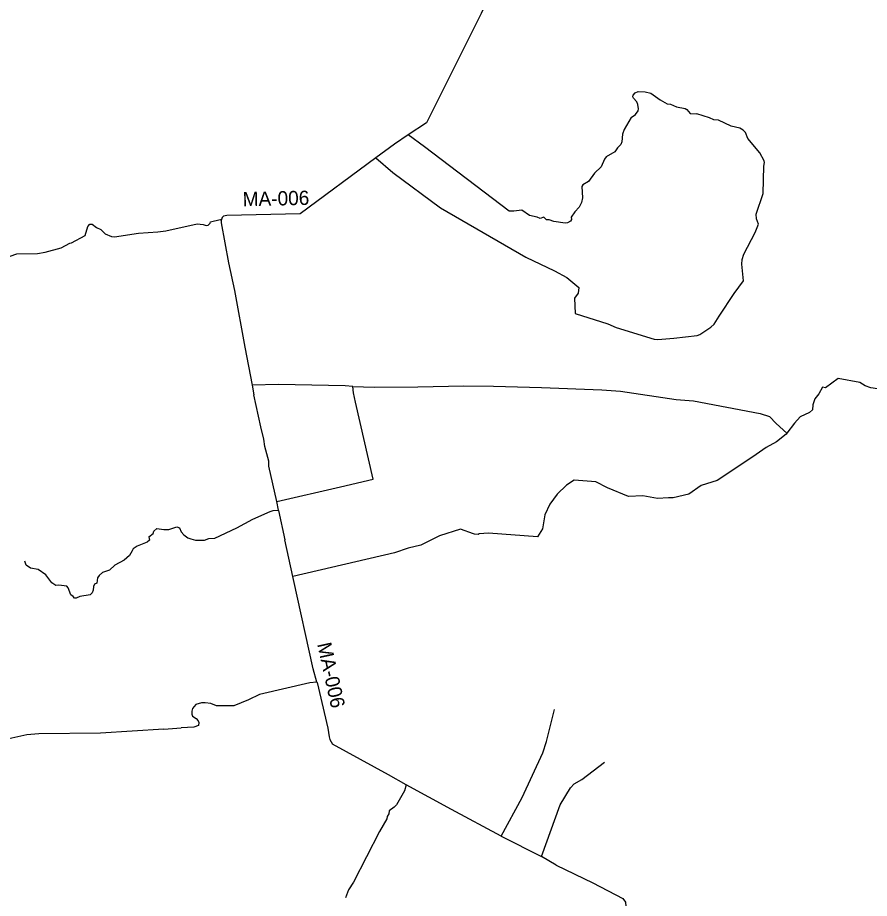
# Model space of a CAD drawing. Extents: x 332 to 501, y 9447 to 9559.
# Drawn here: x 358.33 to 381.07, y 9470.52 to 9494.03 of the extents above; entities that cross this region are included whole.
import ezdxf

# ---------------------------------------------------------------- set-up
doc = ezdxf.new("R2010")
doc.units = 0
for name, color, linetype in [('Level 2', 7, 'Continuous'), ('Level 31', 7, 'Continuous'), ('Level 5', 7, 'Continuous')]:
    doc.layers.add(name, color=color, linetype=linetype)

msp = doc.modelspace()

# ---------------------------------------------------------------- linework, layer by layer
at = {"layer": 'Level 2'}
for points in [[(370.6661, 9496.9394), (371.4317, 9495.8895), (371.441, 9495.7173), (370.7059, 9494.1339), (369.2463, 9491.221), (368.7582, 9490.8961)], [(368.7582, 9490.8961), (368.393, 9490.6531), (367.8945, 9490.2849)], [(367.8945, 9490.2849), (365.8781, 9488.7948), (363.9176, 9488.7487), (363.8245, 9488.7254), (363.7966, 9488.6928), (363.7677, 9488.6105)], [(363.7677, 9488.6105), (363.764, 9488.5484), (363.9584, 9487.4823), (364.1226, 9486.7456)], [(364.1226, 9486.7456), (364.401, 9485.2331)], [(364.401, 9485.2331), (364.5932, 9484.2177)], [(364.5932, 9484.2177), (364.6419, 9483.9606)], [(365.2484, 9481.1136), (365.0374, 9482.053), (365.0374, 9482.1898), (364.9338, 9482.5836), (364.9096, 9482.7777), (364.8214, 9483.1053), (364.6419, 9483.9606)], [(365.2987, 9480.8784), (365.2484, 9481.1136)], [(365.2998, 9480.873), (365.2987, 9480.8784)], [(365.2998, 9480.873), (365.469, 9480.085)], [(365.6771, 9479.1125), (365.469, 9480.085)], [(365.6964, 9479.0285), (365.6771, 9479.1125)], [(366.324, 9476.2857), (366.224, 9476.649), (365.6964, 9479.0285)], [(366.3253, 9476.2811), (366.324, 9476.2857)], [(366.3253, 9476.2811), (366.6141, 9475.064), (366.6494, 9474.8301), (366.6714, 9474.7573), (366.7415, 9474.6318)], [(368.238, 9473.8136), (366.7415, 9474.6318)], [(368.707, 9473.5468), (368.238, 9473.8136)], [(369.914, 9472.889), (368.707, 9473.5468)], [(371.2447, 9472.1745), (369.914, 9472.889)], [(371.2447, 9472.1745), (372.316, 9471.636)], [(372.7099, 9471.4064), (372.316, 9471.636)], [(372.7099, 9471.4064), (373.6851, 9470.9313), (374.4884, 9470.5166), (374.5632, 9470.4133), (374.5736, 9470.2997), (374.4497, 9469.7952), (374.4537, 9469.7528)]]:
    msp.add_lwpolyline(points, dxfattribs=at)
at = {"layer": 'Level 5'}
for points in [[(374.7086, 9491.3635), (374.8305, 9491.4452), (374.8977, 9491.5422), (374.9126, 9491.5907), (374.8939, 9491.7063), (374.8604, 9491.7772), (374.7746, 9491.8742), (374.7597, 9491.9115), (374.7671, 9491.96), (374.8156, 9492.0234), (374.9014, 9492.0569), (375.0842, 9492.0458), (375.2371, 9492.0085), (375.4833, 9491.8332), (375.6735, 9491.7287), (375.7667, 9491.7138), (375.9197, 9491.6467), (376.1546, 9491.6019), (376.1957, 9491.5795), (376.2852, 9491.4714), (376.467, 9491.456)], [(377.065, 9486.059), (377.461, 9486.66), (377.715, 9486.999), (377.665, 9487.447), (377.677, 9487.569), (377.722, 9487.715), (378.026, 9488.292), (378.114, 9488.517), (378.062, 9488.658), (378.053, 9488.778), (378.238, 9489.333), (378.257, 9490.067), (378.273, 9490.16), (378.264, 9490.205), (378.146, 9490.416), (377.826, 9490.801), (377.763, 9490.963), (377.703, 9491.028), (377.612, 9491.074), (377.385, 9491.135), (377.041, 9491.295), (376.923, 9491.3), (376.803, 9491.355), (376.467, 9491.456)], [(374.7086, 9491.3635), (374.523, 9491.041), (374.485, 9490.921), (374.46, 9490.712), (374.436, 9490.643), (374.348, 9490.553), (374.278, 9490.448), (374.049, 9490.309), (374.005, 9490.249), (373.915, 9490.043), (373.732, 9489.874), (373.575, 9489.656), (373.425, 9489.569), (373.397, 9489.519), (373.415, 9489.214), (373.39, 9489.091), (373.327, 9488.968), (373.212, 9488.844), (373.114, 9488.705), (373.119, 9488.637), (373.089, 9488.592), (373.016, 9488.553), (372.955, 9488.545), (372.649, 9488.583), (372.524, 9488.629), (372.456, 9488.633), (372.385, 9488.699), (372.285, 9488.668), (372.203, 9488.704), (372, 9488.747), (371.792, 9488.884), (371.576, 9488.859), (371.458, 9488.866), (369.191, 9490.581)], [(369.191, 9490.581), (368.7582, 9490.8961)], [(367.8945, 9490.2849), (368.3532, 9489.8971), (369.6239, 9488.9493), (371.8984, 9487.6382), (372.6644, 9487.2663), (372.9938, 9487.09), (373.3193, 9486.8216), (373.2989, 9486.671), (373.2032, 9486.5368), (373.2185, 9486.1304), (374.0879, 9485.8544), (374.3084, 9485.7565)], [(359.7218, 9488.0083), (359.7733, 9488.015), (360.132, 9488.21), (360.209, 9488.451), (360.263, 9488.514), (360.322, 9488.519), (360.437, 9488.427), (360.553, 9488.374), (360.671, 9488.259), (360.835, 9488.188), (360.922, 9488.179), (361.563, 9488.275), (362.074, 9488.309), (362.292, 9488.341), (363.127, 9488.521), (363.286, 9488.508), (363.364, 9488.48), (363.419, 9488.49), (363.469, 9488.538), (363.484, 9488.581), (363.739, 9488.637), (363.7677, 9488.6105)], [(358.1343, 9487.6641), (358.3133, 9487.7232), (358.8617, 9487.7355), (359.0651, 9487.7663), (359.4903, 9487.8834), (359.7218, 9488.0083)], [(374.3084, 9485.7565), (375.324, 9485.445), (375.424, 9485.437), (375.851, 9485.475), (376.471, 9485.546), (376.542, 9485.567), (376.836, 9485.761), (376.927, 9485.841), (377.065, 9486.059)], [(381.9568, 9484.0506), (381.8808, 9484.0124), (381.5851, 9484.0998), (381.5059, 9484.1373), (381.2893, 9484.1207), (381.1144, 9484.1457), (380.9622, 9484.2029), (380.8166, 9484.2922), (380.2437, 9484.3955), (379.898, 9484.1498), (379.8189, 9484.1623), (379.7273, 9483.9832), (379.619, 9483.8541), (379.5606, 9483.6916), (379.5565, 9483.5625), (379.4732, 9483.4833), (379.224, 9483.376)], [(367.2821, 9484.1828), (367.077, 9484.202), (365.295, 9484.234), (364.5932, 9484.2177)], [(367.825, 9481.708), (367.353, 9483.763), (367.299, 9484.013), (367.2821, 9484.1828)], [(367.2821, 9484.1828), (367.848, 9484.16), (369.0132, 9484.1716)], [(369.0132, 9484.1716), (370.246, 9484.2), (371.034, 9484.192), (372.316, 9484.152)], [(372.316, 9484.152), (373.929, 9484.089), (374.426, 9484.053), (375.915, 9483.837), (376.376, 9483.798), (378.159, 9483.458), (378.4059, 9483.3827)], [(378.4059, 9483.3827), (378.5811, 9483.1922), (378.8693, 9482.9327)], [(379.224, 9483.376), (379.071, 9483.201), (378.8693, 9482.9327)], [(378.8693, 9482.9327), (378.855, 9482.906)], [(378.855, 9482.906), (378.593, 9482.705), (378.321, 9482.552), (377.963, 9482.307)], [(377.963, 9482.307), (377.009, 9481.674), (376.586, 9481.541), (376.25, 9481.31), (375.836, 9481.211), (375.711, 9481.21)], [(365.2484, 9481.1136), (366.954, 9481.505)], [(366.954, 9481.505), (367.825, 9481.708)], [(375.711, 9481.21), (375.416, 9481.19), (375.025, 9481.267), (374.646, 9481.241), (374.084, 9481.479), (373.77, 9481.637), (373.192, 9481.677), (372.988, 9481.551), (372.734, 9481.31), (372.545, 9481.041), (372.411, 9480.758), (372.3499, 9480.3785), (372.2149, 9480.1685), (370.908, 9480.262), (370.659, 9480.251)], [(361.8371, 9480.1682), (361.9487, 9480.2559), (361.9726, 9480.3196), (362.0523, 9480.3914), (362.2356, 9480.3675), (362.3711, 9480.3675), (362.5783, 9480.4392), (362.658, 9480.4073), (362.6979, 9480.3037), (362.7696, 9480.224), (362.8732, 9480.1443), (362.9529, 9480.1124), (363.0804, 9480.0805), (363.3196, 9480.0805), (363.4391, 9480.1283), (363.5985, 9480.1363), (364.187, 9480.4126), (364.6105, 9480.6388), (365.073, 9480.8457), (365.1527, 9480.8696), (365.2987, 9480.8784)], [(370.506, 9480.248), (370.158, 9480.371), (369.598, 9480.194), (369.093, 9479.95), (368.761, 9479.869), (368.394, 9479.742), (365.6771, 9479.1125)], [(361.8371, 9480.1682), (361.856, 9480.0783), (361.7862, 9480.0218), (361.5238, 9479.9155), (361.4142, 9479.8491), (361.3934, 9479.7911), (361.3154, 9479.6731), (361.1775, 9479.5436), (360.9251, 9479.414), (360.7822, 9479.2778), (360.5978, 9479.213), (360.5131, 9479.1383), (360.4633, 9479.0768), (360.445, 9478.9273), (360.3869, 9478.9007), (360.3553, 9478.8409), (360.352, 9478.7413), (360.3204, 9478.6699), (360.269, 9478.6234), (359.9932, 9478.5802), (359.8969, 9478.5303), (359.8488, 9478.5321), (359.8189, 9478.5736), (359.7525, 9478.6202), (359.6844, 9478.8095), (359.6428, 9478.8494), (359.4302, 9478.8743), (359.3505, 9478.8676), (359.2425, 9478.9441), (359.0848, 9479.1567), (358.8789, 9479.2946), (358.6713, 9479.3311), (358.5583, 9479.4159), (358.5284, 9479.5155)], [(370.5314, 9480.2383), (370.506, 9480.248)], [(370.659, 9480.251), (370.627, 9480.2306), (370.5314, 9480.2383)], [(366.324, 9476.2857), (366.1356, 9476.268), (364.792, 9475.962), (364.495, 9475.816), (364.107, 9475.661), (363.6413, 9475.6564)], [(363.6413, 9475.6564), (363.4923, 9475.716), (363.3385, 9475.7402), (363.2441, 9475.7358), (363.0926, 9475.6897), (363.0004, 9475.5821), (362.9806, 9475.5118), (362.985, 9475.4305), (363.0048, 9475.3822), (363.0992, 9475.3164), (363.1541, 9475.2527), (363.1695, 9475.211), (363.1629, 9475.1341), (363.0355, 9475.088), (362.7006, 9475.0668)], [(371.2447, 9472.1745), (371.803, 9473.209), (372.356, 9474.407), (372.453, 9474.709), (372.6651, 9475.5552)], [(362.2343, 9475.0311), (360.541, 9474.928), (358.901, 9474.908), (358.581, 9474.879), (357.61, 9474.667)], [(362.2343, 9475.0311), (362.7006, 9475.0668)], [(373.19, 9473.574), (373.3945, 9473.6871), (374.0027, 9474.1538)], [(368.707, 9473.5468), (368.665, 9473.3917), (368.4485, 9473.0137), (368.3871, 9472.949), (368.2546, 9472.8586), (368.2385, 9472.7713), (368.1965, 9472.7002), (368.1868, 9472.6453), (367.9897, 9472.306), (367.295, 9470.9522), (367.1657, 9470.7422), (367.0882, 9470.5289)], [(372.316, 9471.636), (372.813, 9473.013), (373.097, 9473.466), (373.19, 9473.574)]]:
    msp.add_lwpolyline(points, dxfattribs=at)

# ---------------------------------------------------------------- texts
at = {"layer": 'Level 31'}
for rotation, p in [(1.23388, (364.3445, 9488.9928)), (282.41084, (366.3275, 9477.3067))]:
    msp.add_text('MA-006', height=0.38, rotation=rotation, dxfattribs=at).set_placement(p)

doc.saveas('drawing.dxf')
